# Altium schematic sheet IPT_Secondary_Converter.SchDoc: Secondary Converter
size A3; Author: Pranav G & Manoj K; Organization: University Of Auckland; Address1: 20 Symonds Street,; Address2: Auckland CBD,; Address3: Auckland 1010,; Address4: New Zealand; DocumentNumber: 1; Revision: 1; SheetNumber: 1; SheetTotal: 1
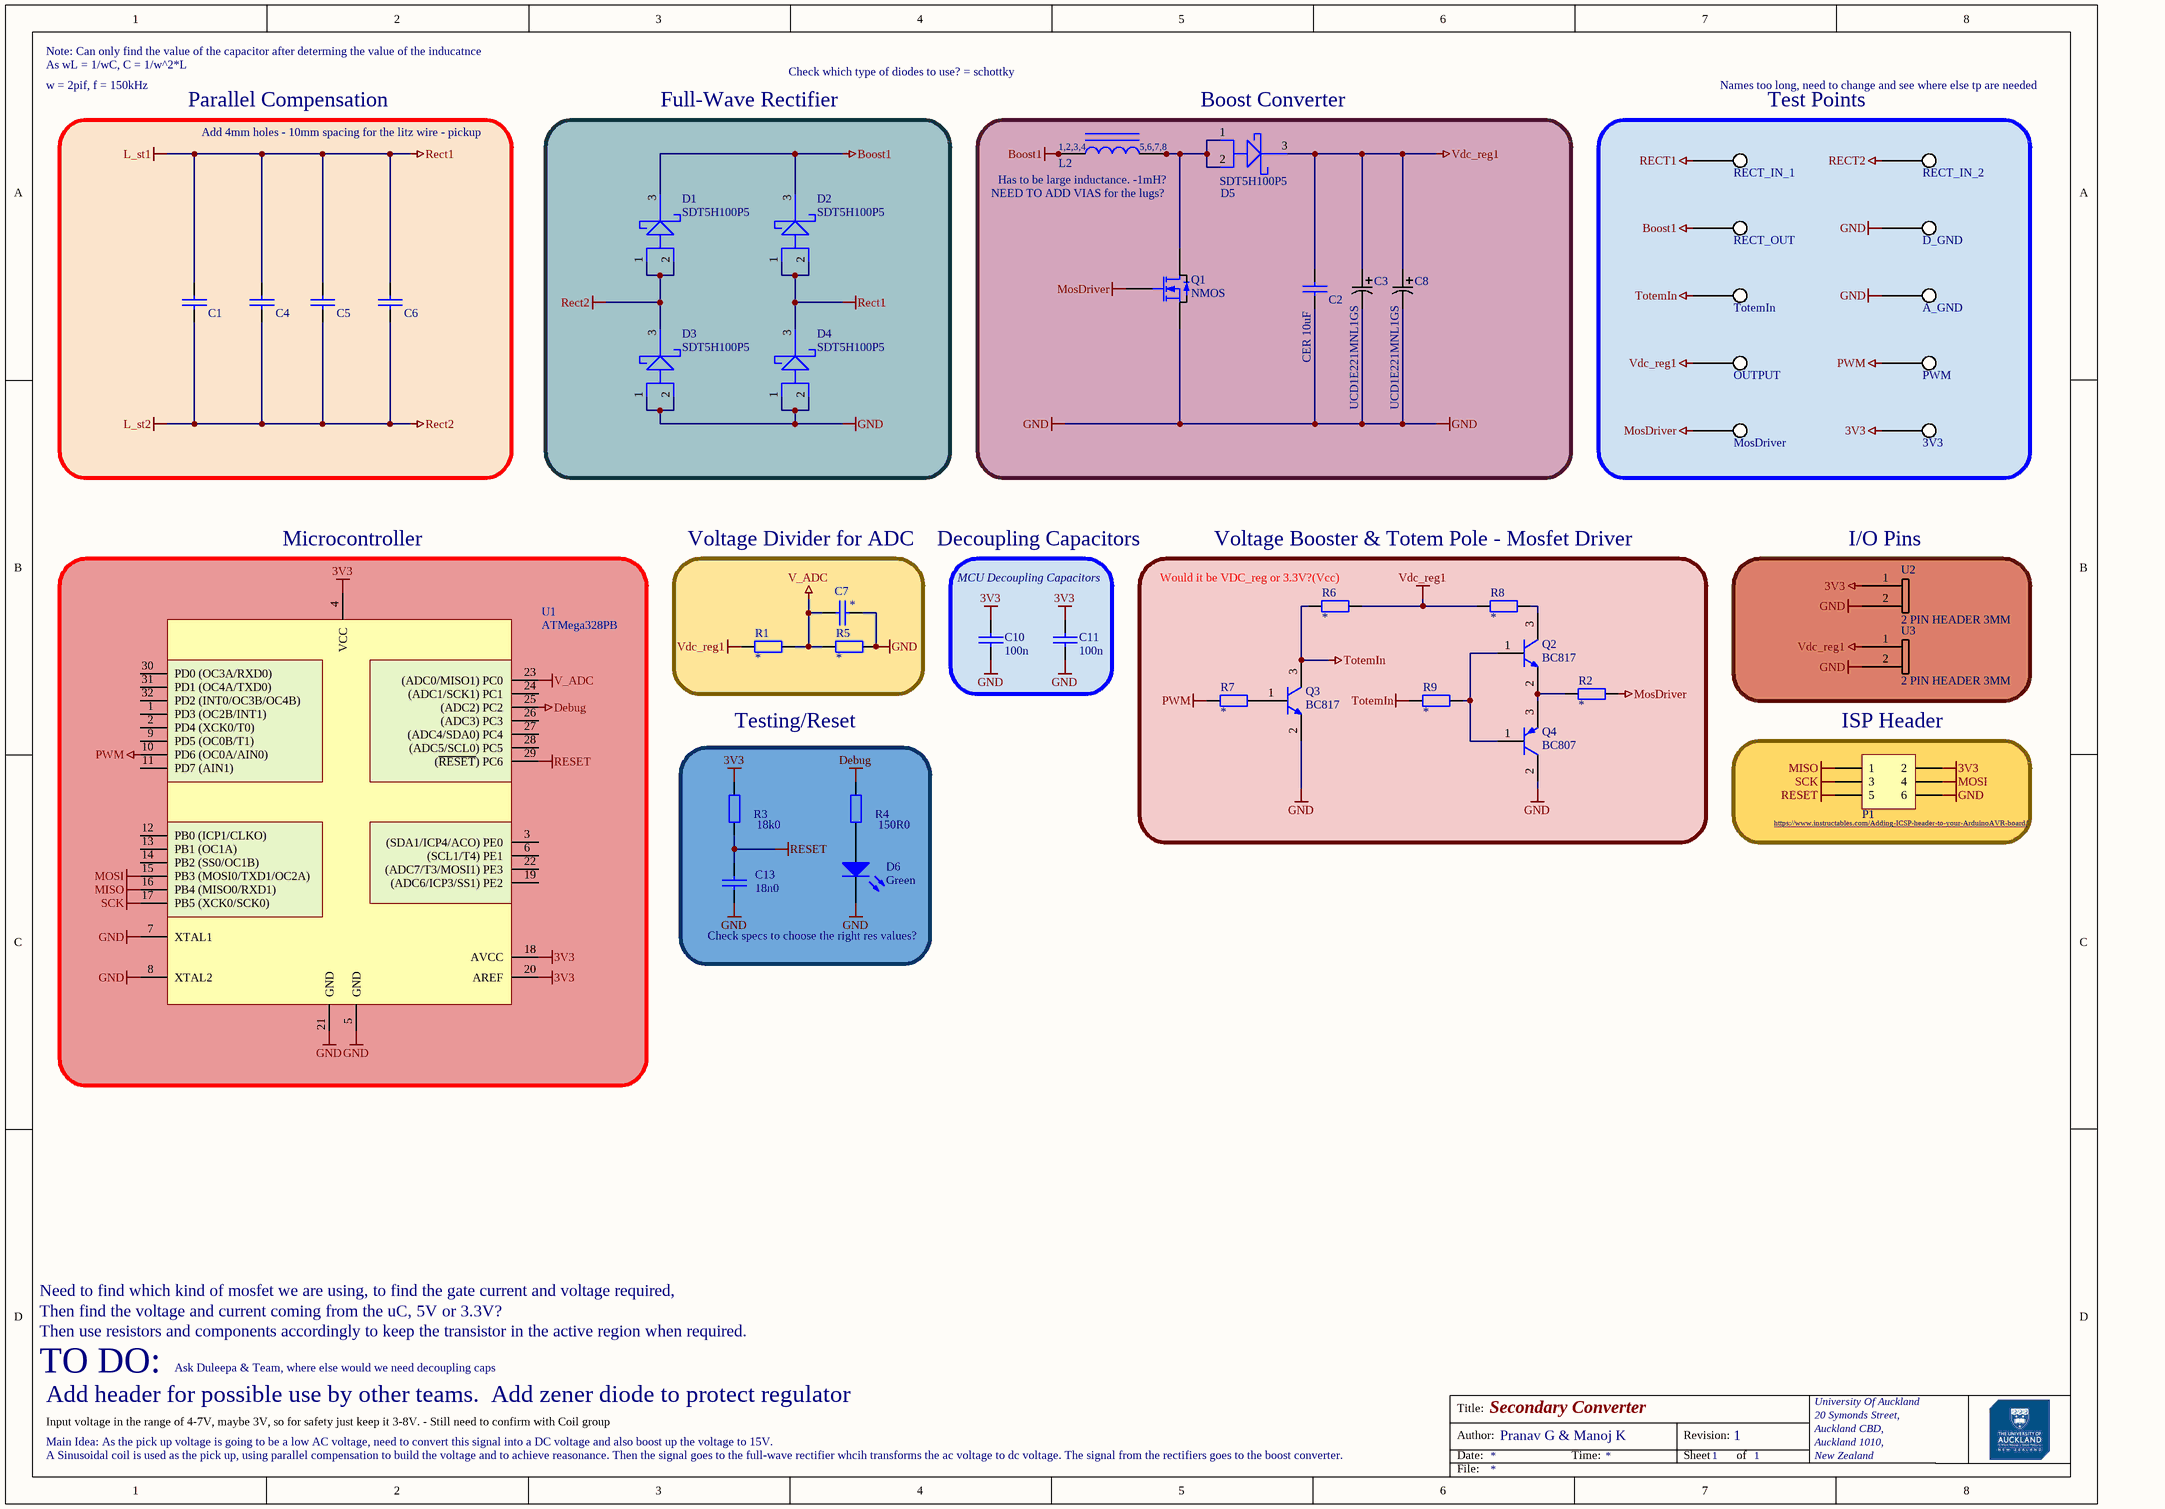
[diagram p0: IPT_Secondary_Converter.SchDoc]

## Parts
3V3  TP_DIR  [TP5015]  (value not drawn)
A_GND  TP_GND  [TP5015]  (value not drawn)
C1  CCAP5750  [C5750]  (value not drawn)
C2  CER 10uF  [C1210]
C3  UCD1E221MNL1GS  [PCAP_8x10-ELECT_NCA]
C4  CCAP5750  [C5750]  (value not drawn)
C5  CCAP5750  [C5750]  (value not drawn)
C6  CCAP5750  [C5750]  (value not drawn)
C7  *  [C0805]
C8  UCD1E221MNL1GS  [PCAP_8x10-ELECT_NCA]
C10  100n  [C0805]
C11  100n  [C0805]
C13  18n0  [C0805]
D1  SDT5H100P5  [DIO_PDS360-13]
D2  SDT5H100P5  [DIO_PDS360-13]
D3  SDT5H100P5  [DIO_PDS360-13]
D4  SDT5H100P5  [DIO_PDS360-13]
D5  SDT5H100P5  [DIO_PDS360-13]
D6  Green  [LED]
D_GND  TP_GND  [TP5015]  (value not drawn)
L2  Inductor  [EFD20]  (value not drawn)
MosDriver  TP_DIR  [TP5015]  (value not drawn)
OUTPUT  TP_DIR  [TP5015]  (value not drawn)
P1  HDR3X2  [HDR2X3_2P54]  (value not drawn)
PWM  TP_DIR  [TP5015]  (value not drawn)
Q1  NMOS  [BSC072N08NS5ATMA1_modified_v2]
Q2  BC817  [SOT95P230X110-3N]
Q3  BC817  [SOT95P230X110-3N]
Q4  BC807  [SOT95P230X110-3N]
R1  *  [0805 RES]
R2  *  [0805 RES]
R3  18k0  [R0805]
R4  150R0  [R0805]
R5  *  [0805 RES]
R6  *  [0805 RES]
R7  *  [0805 RES]
R8  *  [0805 RES]
R9  *  [0805 RES]
RECT_IN_1  TP_DIR  [TP5015]  (value not drawn)
RECT_IN_2  TP_DIR  [TP5015]  (value not drawn)
RECT_OUT  TP_TX  [TP5015]  (value not drawn)
TotemIn  TP_GND  [TP5015]  (value not drawn)
U1  ATMega328PB  [TQFP32]
U2  2 PIN HEADER 3MM  [3mm_holes]
U3  2 PIN HEADER 3MM  [3mm_holes]

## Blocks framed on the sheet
Parallel Compensation: C1 C4-C6
Full-Wave Rectifier: D1-D4
Boost Converter: C2 C3 C8 D5 L2 Q1
Test Points: 3V3 A_GND D_GND MosDriver OUTPUT PWM RECT_IN_1 RECT_IN_2 RECT_OUT TotemIn
Microcontroller: U1
Voltage Divider for ADC: C7 R1 R5
MCU Decoupling Capacitors: C10 C11
Voltage Booster & Totem Pole - Mosfet Driver: Q2-Q4 R2 R6-R9
I/O Pins: U2 U3
Testing/Reset: C13 D6 R3 R4
ISP Header: P1

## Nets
3V3: 3V3.1 C10.2 C11.2 P1.2 R3.2 U1.4(VCC) U1.18(AVCC) U1.20(AREF) U2.1
Boost1: D1.3 D2.3 L2.1 L2.2 L2.3 L2.4 RECT_OUT.1
Debug: R4.2 U1.25((ADC2)_PC2)
GND: A_GND.1 C2.1 C3.2 C7.1 C8.2 C10.1 C11.1 C13.1 D3.1 D3.2 D4.1 D4.2 D6.2(K) D_GND.1 P1.6 Q1.1(S) Q3.2 Q4.2 R5.2 U1.5(GND) U1.7(XTAL1) U1.8(XTAL2) U1.21(GND) U2.2 U3.2
L_st1: C1.2 C4.2 C5.2 C6.2 D2.1 D2.2 D4.3 RECT_IN_1.1  [also labelled Rect1]
L_st2: C1.1 C4.1 C5.1 C6.1 D1.1 D1.2 D3.3 RECT_IN_2.1  [also labelled Rect2]
MISO: P1.1 U1.16(PB4_(MISO0/RXD1))
MosDriver: MosDriver.1 Q1.4(G) R2.2
MOSI: P1.4 U1.15(PB3_(MOSI0/TXD1/OC2A))
PWM: PWM.1 R7.1 U1.10(PD6_(OC0A/AIN0))
RESET: C13.2 P1.5 R3.1 U1.29((~{RESET})_PC6)
SCK: P1.3 U1.17(PB5_(XCK0/SCK0))
TotemIn: Q3.3 R6.2 R9.2 TotemIn.1
V_ADC: C7.2 R1.2 R5.1 U1.23((ADC0/MISO1)_PC0)
Vdc_reg1: C2.2 C3.1 C8.1 D5.3 OUTPUT.1 R1.1 R6.1 R8.2 U3.1
NetD5_1: D5.1 D5.2 L2.5 L2.6 L2.7 L2.8 Q1.8(D)
NetD6_1: D6.1(A) R4.1
NetQ2_1: Q2.1 Q4.1 R9.1
NetQ2_2: Q2.2 Q4.3 R2.1
NetQ2_3: Q2.3 R8.1
NetQ3_1: Q3.1 R7.2

Not connected (* = marked no-connect by the designer): U1 1(PD3_(OC2B/INT1)) 2(PD4_(XCK0/T0)) 3((SDA1/ICP4/ACO)_PE0) 6((SCL1/T4)_PE1) 9(PD5_(OC0B/T1)) 11(PD7_(AIN1)) 12(PB0_(ICP1/CLKO)) 13(PB1_(OC1A)) 14(PB2_(SS0/OC1B)) 19((ADC6/ICP3/SS1)_PE2) 22((ADC7/T3/MOSI1)_PE3) 24((ADC1/SCK1)_PC1) 26((ADC3)_PC3) 27((ADC4/SDA0)_PC4) 28((ADC5/SCL0)_PC5) 30(PD0_(OC3A/RXD0)) 31(PD1_(OC4A/TXD0)) 32(PD2_(INT0/OC3B/OC4B))

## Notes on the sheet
- Note: Can only find the value of the capacitor after determing the value of the inducatnce
- As wL = 1/wC, C = 1/w^2*L
- w = 2pif, f = 150kHz
- Check which type of diodes to use? = schottky
- Names too long, need to change and see where else tp are needed
- Add 4mm holes - 10mm spacing for the litz wire - pickup
- Has to be large inductance. -1mH?
- NEED TO ADD VIAS for the lugs?
- Decoupling Capacitors
- (near R6) Would it be VDC_reg or 3.3V?(Vcc)
- (near P1) https://www.instructables.com/Adding-ICSP-header-to-your-ArduinoAVR-board/
- Check specs to choose the right res values?
- Need to find which kind of mosfet we are using, to find the gate current and voltage required,
- Then find the voltage and current coming from the uC, 5V or 3.3V?
- TO DO:
- Then use resistors and components accordingly to keep the transistor in the active region when required.
- Ask Duleepa & Team, where else would we need decoupling caps
- A Sinusoidal coil is used as the pick up, using parallel compensation to build the voltage and to achieve reasonance. Then the signal goes to the full-wave rectifier whcih transforms the ac voltage to dc voltage. The signal from the rectifiers goes to the boost converter.
- Main Idea: As the pick up voltage is going to be a low AC voltage, need to convert this signal into a DC voltage and also boost up the voltage to 15V.
- Add header for possible use by other teams.  Add zener diode to protect regulator
- Input voltage in the range of 4-7V, maybe 3V, so for safety just keep it 3-8V. - Still need to confirm with Coil group

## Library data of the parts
3V3 A_GND D_GND MosDriver OUTPUT PWM RECT_IN_1 RECT_IN_2 RECT_OUT TotemIn = TP_5015: SM Test Point 5015
C1 C4 C5 = CCAP5750: CCAP1210
C2 = CCAP1210: Ceramic, 10uF
C3 C8 = UCD1E221MNL1GS: 220µF 25V Aluminum Electrolytic Capacitors Radial, Can - SMD 5000 Hrs @ 105°C; Vendor: Nichicon; Built_By: EMA_UL_Team; SourceLibrary: Nichicon_2011-10-21; Type: DEV
C6 = CCAP5750: https://product.tdk.com/info/en/documents/chara_sheet/C5750X7R2E474K230KM.pdf
C7 C10 C11 C13 = CCAP0805
D1-D5 = SDT5H100P5-7DICT-ND
D6 = LED_TH_2P54: Typical throughole GaAs LED with 2.54mm pitch; Manufacturer: Generic Components; Class I: Optoelectronic
L2 = Inductor EFD20: Inductor with core
P1 = HDR3X2: Header, 3-Pin, Dual row
Q1 = NMOS OptiMOS BSC072N08NS5ATMA1: MOSFET N-CH 80V 74A 8TDSON; Manufacturer: Infineon Technologies; Type: Surface mount
Q2 Q3 = BC817: BC817-40,215. NPN GP 500 45V SOT23
Q4 = BC807: BC807-40,215.  PNP GP 500MA 45V SOT23
R1 R2 R5-R9 = Res_SMT_0805: 0805 resistor
R3 R4 = RES0805
U1 = ATMega328PB: IC MCU 8BIT 32KB FLASH 32TQFP
U2 U3 = HEADER_2PIN: 3MM HOLES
